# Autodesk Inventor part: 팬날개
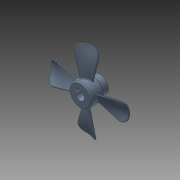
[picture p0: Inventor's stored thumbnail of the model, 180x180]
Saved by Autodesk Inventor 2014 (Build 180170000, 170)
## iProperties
Company: 한국ATC센터
Created: 2016-06
Part Number: 팬날개
Document SubType Name: Modeling
Designer: mdu
Density: 1.06 g/cm^3
Material: ABS 플라스틱
Mass: 29.2865 g
Surface Area: 147.726 cm^2
Volume: 27.6288 cm^3
Appearance: 강청색
Author: mdu
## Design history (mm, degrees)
sketch "스케치1"
  geometry: L1 (-15, 0)-(15, 0); L2 (-15, 0)-(-15, 17); L3 (-15, 17)-(5, 17); L4 (5, 17)-(5, 13); L5 (5, 13)-(15, 13); L6 (15, 13)-(15, 0); 2 further points
  constraints: 12 end point, 3 parallel, 2 perpendicular, 1 coincident, 1 horizontal, 1 midpoint
  dimensions: "d0" = 30 distance of L1.start L1.end; "d8" = 34 diameter of L3 L1; "d10" = 26 diameter of L5 L1; "d32" = 20 distance of L2.end L3.end
revolve "회전1" sketch "스케치1" stored, may be unused: angle "d11" = 90 deg
node "작업 평면2"
sketch "스케치7"
  geometry: L1 (-15, 17)-(5, 17) reference; L2 (-15, -17)-(5, -17) reference; L3 (-5, 17)-(-5, -17); A1 r 35 centre (-36.399, -13.457) between (-2, -7) and (-8, 7); 1 further point
  constraints: 2 end point, 2 midpoint, 2 point on circle, 1 centre point
  dimensions: "d36" = 35 radius of A1; "d37" = 10 distance from line of A1.start L2; "d38" = 10 distance from line of A1.end L1; "d45" = 3 distance from line of A1.end L3; "d46" = 3 distance from line of A1.start L3
sketch "3D 스케치1"
  geometry: L1 through (0, 0) direction (1, 0) reference; L2 through (0, 0) direction (1, 0) reference; 13 other entities
  constraints: 2 collinear
  node "투영 원본 위치 스케치7"
sketch "스케치8"
  geometry: L1 (-15, 17)-(5, 17) reference; L2 (-15, -17)-(5, -17) reference; L3 (-5, 17)-(-5, -17); A1 r 30 centre (-28.74, -3.591) between (-3, -19) and (-9, 19); 1 further point
  constraints: 2 end point, 2 midpoint, 2 point on circle, 1 centre point
  dimensions: "d43" = 30 radius of A1; "d47" = 4 distance from line of A1.end L3; "d48" = 2 distance from line of A1.start L3; "d58" = 2 distance from line of A1.end L1; "d59" = 2 distance from line of A1.start L2
sketch "3D 스케치2"
sketch "3D 스케치3"
feature "경계 패치1" sketch "3D 스케치2", "3D 스케치3" dims "d50" = 0
feature "연장1" dims "d55" = 2
feature "두껍게 하기1" dims "d51" = 2, "d52" = 2
sketch "스케치9"
  geometry: C1 r 59 at (0, 0); 1 further point
  constraints: 1 centre point, 1 coincident
  dimensions: "d60" = 118 diameter of C1
extrude "돌출2" sketch "스케치9" distance "d62" = 200; taper "d63" = 0 deg
fillet "모깎기6" dims "d64" = 10
fillet "모깎기7" dims "d66" = 0.8
fillet "모깎기8" dims "d67" = 0.8
sketch "스케치2"
  geometry: L1 (-2.5, 6)-(-2.5, 8.8); L2 (-2.5, 8.8)-(2.5, 8.8); L3 (2.5, 8.8)-(2.5, 6); A1 r 6.5 centre (0, 0) between (-2.5, 6) and (2.5, 6); 1 further point
  constraints: 6 end point, 2 parallel, 2 point on circle, 1 centre point, 1 coincident, 1 horizontal, 1 vertical
  dimensions: "d12" = 13 diameter of A1; "d13" = 5 distance of L1.end L2.end; "d14" = 15.3 dimension on A1 L2 (computed from d12)
extrude "돌출1" cut sketch "스케치2" stored distance "d15" = 10; taper "d16" = 0 deg
chamfer "모따기1" distance "d17" = 1; stored, may be unused: second distance "d18" = 2, angle "d19" = 45 deg
node "작업 평면1"
fillet "모깎기9" dims "d77" = 2
fillet "모깎기10" dims "d78" = 2
fillet "모깎기11" dims "d79" = 2
node "솔리드1"
pattern_circular "원형 패턴1" dims "d69" = 360 deg
pattern_circular "원형 패턴2" dims angle "d72" = 360 deg
pattern_circular "원형 패턴3" dims angle "d75" = 360 deg
node "투영 원본 위치 스케치8"
node "곡면1"
node "곡면2"
node "곡면3"
node "곡면4"
feature "경계 패치2"
feature "경계 패치3"
feature "경계 패치4"
